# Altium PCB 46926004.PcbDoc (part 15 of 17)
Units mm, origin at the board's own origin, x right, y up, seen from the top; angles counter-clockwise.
Board outline 250 x 200 mm, 6 copper layers (Top Layer, INT1_GND, INT2_SIG, INT3_SIG, INT4_GND, Bottom Layer), stack 1.71 mm thick; 1450 components, 1293 nets, 5656 pads, 2307 vias.
Unrouted connection lines stored in the file: 2.
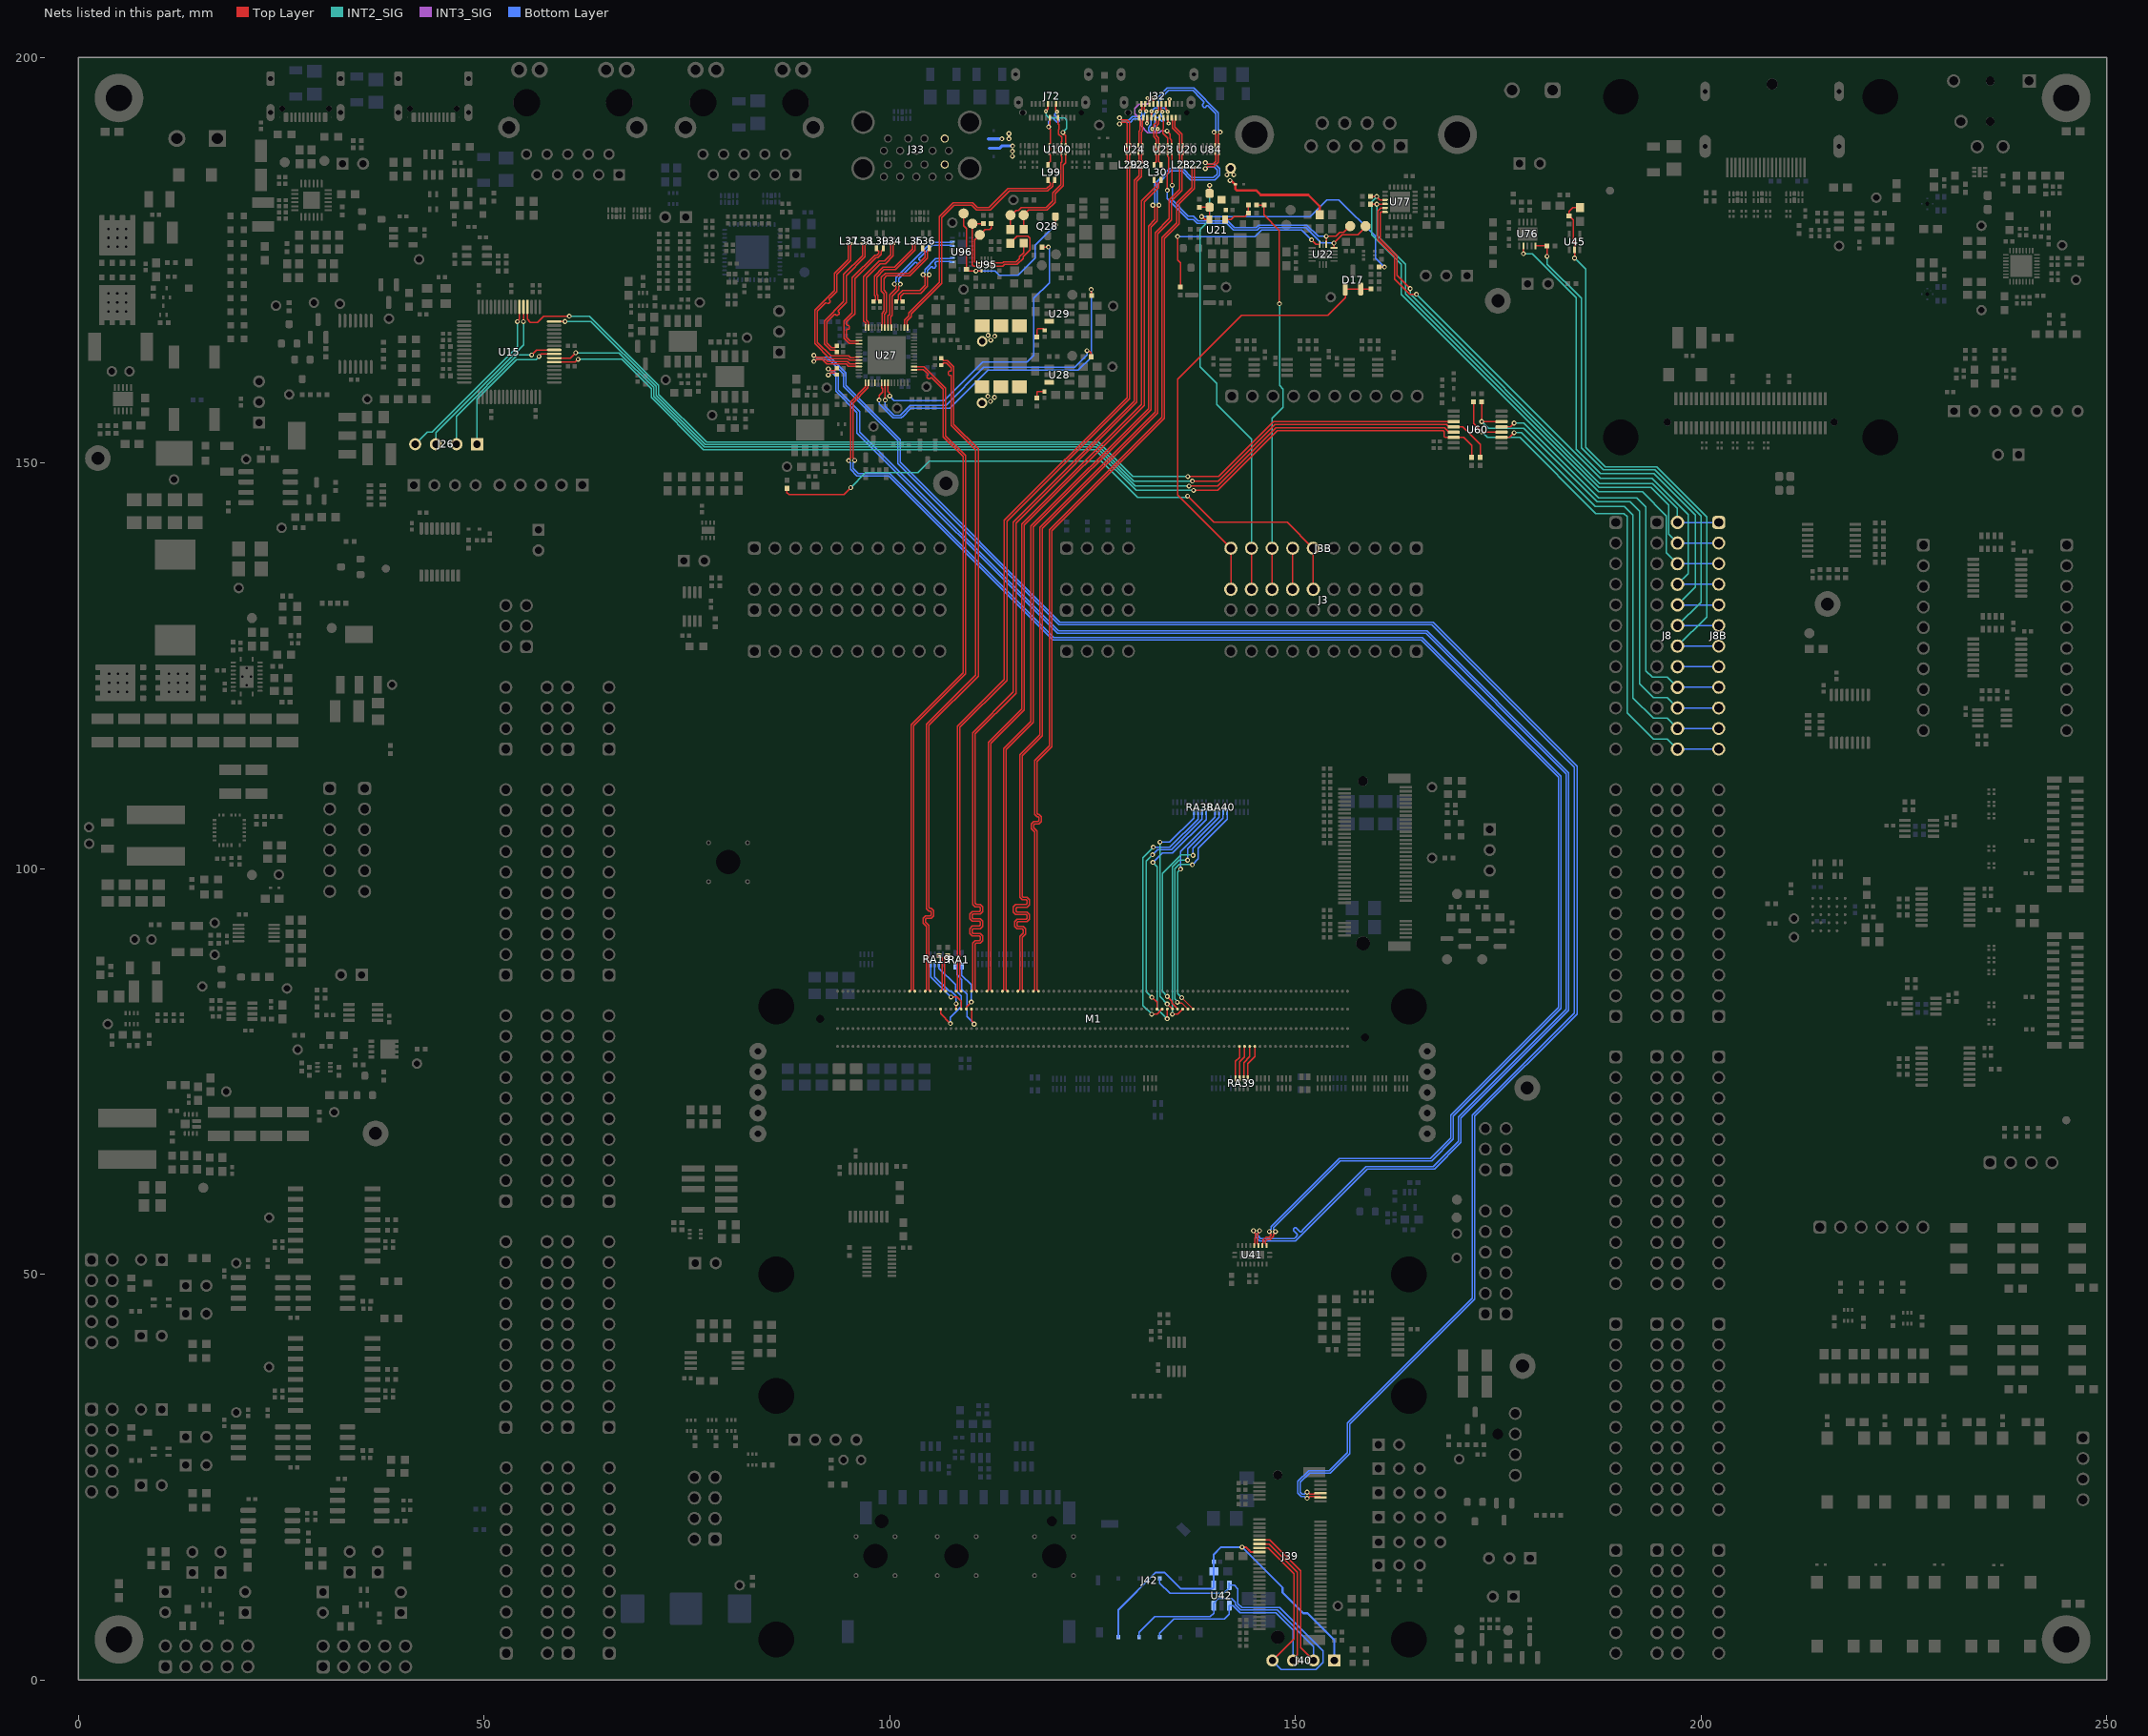
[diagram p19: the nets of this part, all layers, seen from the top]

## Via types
v1: diameter 0.6, hole 0.3, Top Layer to Bottom Layer, tented both sides, 2171 vias
v2: diameter 0.6, hole 0.3, Top Layer to Bottom Layer, 48 vias
v3: diameter 1, hole 0.5, Top Layer to Bottom Layer, tented both sides, 37 vias
v4: diameter 0.5, hole 0.2, Top Layer to Bottom Layer, tented both sides, 34 vias
v5: diameter 0.6, hole 0.3, Top Layer to Bottom Layer, tented bottom, 17 vias

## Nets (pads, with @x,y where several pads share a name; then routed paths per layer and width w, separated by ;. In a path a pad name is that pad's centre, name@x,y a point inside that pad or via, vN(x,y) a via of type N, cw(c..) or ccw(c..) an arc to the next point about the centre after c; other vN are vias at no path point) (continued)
SSRX2_N: J32.A10 L28.3 U24.1 U24.10 | length 5.7
  Top Layer w0.15: L28.3@131.15,187.125 131.075,187.2 131.075,187.288 131.05,187.313 131.05,187.996 131.15,188.096 U24.10@131.15,188.283 131.15,188.471 131.05,188.571 131.05,188.83 131.15,188.93 U24.1@131.15,189.117 131.15,189.305 131.05,189.405 131.05,190.809 131.15,190.909 131.15,192.187 131.175,192.212 131.175,192.475 J32.A10@131.25,192.55
SSRX2_P: J32.A11 L28.4 U24.2 U24.9 | length 5.7
  Top Layer w0.15: L28.4@130.65,187.125 130.725,187.2 130.725,187.288 130.75,187.313 130.75,187.996 130.65,188.096 U24.9@130.65,188.283 130.65,188.471 130.75,188.571 130.75,188.83 130.65,188.93 U24.2@130.65,189.117 130.65,189.305 130.75,189.405 130.75,190.933 130.85,191.034 130.85,192.187 130.825,192.212 130.825,192.475 J32.A11@130.75,192.55
SSTX1_N: J32.A3 L23.4 U20.5 U20.6 | length 6
  Top Layer w0.15: J32.A3@134.75,192.55 134.825,192.475 134.825,192.212 134.85,192.187 134.85,191.302 135.735,190.417 135.735,189.405 135.635,189.305 135.635,188.93 135.735,188.83 135.735,188.571 135.635,188.471 135.635,188.096 135.727,188.004 135.727,187.313 135.7,187.286 135.7,187.2 L23.4@135.625,187.125
SSTX1_P: J32.A2 L23.3 U20.4 U20.7 | length 6
  Top Layer w0.15: J32.A2@135.25,192.55 135.175,192.475 135.175,192.212 135.15,192.187 135.15,191.427 136.035,190.541 136.035,189.405 136.135,189.305 136.135,188.93 136.035,188.829 136.035,188.571 136.135,188.471 136.135,188.096 136.027,187.987 136.027,187.313 136.05,187.29 136.05,187.2 L23.3@136.125,187.125
SSTX2_N: J32.B3 L29.4 U24.5 U24.6 | length 11.6
  Top Layer w0.15: v1(128.32,191.805) 128.408,191.805 128.633,192.03 129.107,192.03 129.25,191.887 129.25,189.405 129.15,189.305 U24.5@129.15,189.117 129.15,188.93 129.25,188.83 129.25,188.571 129.15,188.471 U24.6@129.15,188.283 129.15,188.096 129.25,187.996 129.25,187.668 129.25,187.313 129.225,187.288 129.225,187.2 L29.4@129.15,187.125 ; J32.B3@131.5,194.25 131.425,194.175 131.425,193.916 131.396,193.887 131.396,193.613 131.6,193.409 v4(131.6,193.35)
  Bottom Layer w0.15: v1(128.32,191.805) 128.408,191.805 128.633,192.03 129.643,192.03 130.035,192.422 131.043,192.422 131.388,192.766 131.388,193.087 131.6,193.3 v4(131.6,193.35) 131.6,193.285 131.403,193.087
SSTX2_P: J32.B2 L29.3 U24.4 U24.7 | length 11.6
  Top Layer w0.15: v1(128.32,192.555) 128.408,192.555 128.633,192.33 129.231,192.33 129.55,192.011 129.55,189.405 129.65,189.305 U24.4@129.65,189.117 129.65,188.93 129.55,188.829 129.55,188.571 129.65,188.471 U24.7@129.65,188.283 129.65,188.096 129.55,187.995 129.55,187.792 129.55,187.313 129.575,187.288 129.575,187.2 L29.3@129.65,187.125 ; v4(130.875,193.35) 130.875,193.392 131.096,193.613 131.096,193.887 131.075,193.908 131.075,194.175 J32.B2@131,194.25
  Bottom Layer w0.15: v1(128.32,192.555) 128.408,192.555 128.633,192.33 129.519,192.33 129.911,192.722 130.919,192.722 131.088,192.891 131.088,193.087 130.875,193.3 v4(130.875,193.35) 130.875,193.285 131.073,193.087
UART3_CTS_3V: J26.4 U15.54 | length 22.6
  Top Layer w0.15: v1(54.09,167.435) 54.09,167.488 54.35,167.748 U15.54@54.35,169.25
  INT2_SIG w0.15: J26.4@41.515,152.325 43.015,153.825 43.594,153.825 54.09,164.321 v1(54.09,167.435)
UART3_RTS_3V: J26.3 U15.53 | length 21.4
  Top Layer w0.15: v1(54.85,167.435) U15.53@54.85,169.25
  INT2_SIG w0.15: J26.3@44.055,152.325 44.055,153.765 54.85,164.56 v1(54.85,167.435)
UART3_RXD_3V: R454.2 U15.48 U60.12 | length 128.4
  Top Layer w0.15: U15.48@58.65,167.45 v1(59.965,167.45) ; v1(137.3,147.775) 140.464,147.775 147.444,154.755 168.636,154.755 168.936,154.455 U60.12@169.5,154.455 170.629,154.455 172.782,152.303 R454.2@172.782,150.705
  INT2_SIG w0.15: v1(59.965,167.45) 63.19,167.45 71.2,159.44 71.2,158.349 77.277,152.272 125.577,152.272 130.074,147.775 v1(137.3,147.775)
UART3_TXD_3V: U15.52 U60.11 | length 127.8
  Top Layer w0.15: U15.52@55.35,169.25 55.35,168.177 55.325,168.152 55.325,167.718 55.699,167.344 56.574,167.344 57.335,168.105 v1(60.51,168.105) ; v1(136.735,148.328) 140.522,148.328 147.299,155.105 U60.11@169.5,155.105
  INT2_SIG w0.15: v1(60.51,168.105) 62.999,168.105 71.528,159.576 71.528,158.484 77.413,152.6 125.713,152.6 129.984,148.328 v1(136.735,148.328)
UART4_CTS_3V: J26.2 U15.41 | length 18.9
  Top Layer w0.15: v1(55.865,163.325) 56.49,163.95 U15.41@58.65,163.95
  INT2_SIG w0.15: J26.2@46.595,152.325 46.595,155.782 54.138,163.325 v1(55.865,163.325)
UART4_RTS_3V: J26.1 U15.40 | length 17.4
  Top Layer w0.15: v1(56.765,163.15) 56.778,163.15 57.078,163.45 U15.40@58.65,163.45
  INT2_SIG w0.15: J26.1@49.135,152.325 49.135,157.898 54.006,162.769 56.384,162.769 v1(56.765,163.15)
UART4_RXD_3V: R453.2 U15.38 U60.14 | length 126.2
  Top Layer w0.15: U15.38@58.65,162.45 61.235,162.45 v1(61.585,162.8) ; v1(137.436,146.634) 137.471,146.67 140.42,146.67 147.755,154.005 168.204,154.005 168.348,153.861 168.348,153.259 168.452,153.155 U60.14@169.5,153.155 170.75,153.155 171.726,152.179 R453.2@171.726,150.705
  INT2_SIG w0.15: v1(61.585,162.8) 66.992,162.8 70.6,159.192 70.6,158.1 77.028,151.672 125.328,151.672 130.366,146.634 v1(137.436,146.634)
UART4_TXD_3V: U15.39 U60.13 | length 121.8
  Top Layer w0.15: U15.39@58.65,162.95 60.65,162.95 v1(61.3,163.6) ; v1(136.872,147.159) 140.414,147.159 147.61,154.355 168.39,154.355 168.94,153.805 U60.13@169.5,153.805
  INT2_SIG w0.15: v1(61.3,163.6) 66.616,163.6 70.9,159.316 70.9,158.224 77.152,151.972 125.452,151.972 130.265,147.159 v1(136.872,147.159)
UART_1_CTS: M1.B36 RA38.1 | length 30.9
  Top Layer w0.15: v1(134.195,81.501) 134.201,81.507 134.201,82.694 M1.B36@134.207,82.7
  INT2_SIG w0.15: v1@132.4,100.8 132.95,100.25 132.95,82.747 v1(134.195,81.501)
  Bottom Layer w0.15: v1(132.428,100.772) 133.581,101.925 134.84,101.925 138.99,106.075 RA38.1@138.99,107
UART_1_CTS_JMP: J8.8 J8B.4 U77.11 | length 72.8
  Top Layer w0.15: U77.11@161.075,181.45 160.91,181.45 160.885,181.425 160.865,181.445 160.52,181.445 160.14,181.065 160.14,177.49 162.21,175.419 162.21,172.7 164.095,170.815 v1(164.915,170.815)
  INT2_SIG w0.15: v1(164.915,170.815) 187.63,148.1 193.951,148.1 198.4,143.651 198.4,136.37 J8.8@197.09,135.06
  Bottom Layer w0.15: J8.8@197.09,135.06 J8B.4@202.17,135.06
UART_1_RTS: M1.B38 RA38.2 | length 28.7
  Top Layer w0.15: v1(132.308,84.15) 132.937,83.521 M1.B38@132.937,82.7
  INT2_SIG w0.15: v1(132.308,84.15) 131.6,84.858 131.6,100.939 v1(132.383,101.722)
  Bottom Layer w0.15: v1(132.383,101.722) 133.011,102.35 134.74,102.35 138.49,106.1 RA38.2@138.49,107
UART_1_RTS_JMP: J8.6 J8B.3 R384.1 U77.9 | length 71.3
  Top Layer w0.15: R384.1@159.25,182.85 v1(160.018,182.85) 160.418,182.45 U77.9@160.885,182.45 U77.9@161.075,182.45
  INT2_SIG w0.15: v1(160.018,182.85) 159.39,182.222 159.39,178.13 163.036,174.484 163.036,170.792 187.376,146.451 192.746,146.451 195.707,143.49 195.707,138.982 J8.6@197.09,137.6
  Bottom Layer w0.15: J8.6@197.09,137.6 J8B.3@202.17,137.6
UART_1_RXD: M1.B35 RA38.4 | length 27.4
  Top Layer w0.15: v1(134.195,83.328) 134.214,83.328 M1.B35@134.842,82.7
  INT2_SIG w0.15: v1(133.293,103.275) 133.293,84.23 v1(134.195,83.328)
  Bottom Layer w0.15: v1(133.293,103.275) 134.512,103.275 137.49,106.253 RA38.4@137.49,107
UART_1_RXD_JMP: J8.2 J8B.1 U77.12 | length 62.9
  Top Layer w0.15: U77.12@161.075,180.95 U77.12@160.885,180.95 160.558,180.95 160.44,180.832 160.44,177.614 162.51,175.544 162.51,173.143 v1(164.15,171.503)
  INT2_SIG w0.15: v1(164.15,171.503) 164.15,170.838 187.488,147.5 194,147.5 197.09,144.41 J8.2@197.09,142.68
  Bottom Layer w0.15: J8.2@197.09,142.68 J8B.1@202.17,142.68
UART_1_TXD: M1.B37 RA38.3 | length 30.9
  Top Layer w0.15: v1(132.287,82.072) 132.944,82.072 M1.B37@133.572,82.7
  INT2_SIG w0.15: v1(132.287,82.072) 131.199,83.16 131.199,101.369 v1(132.481,102.65)
  Bottom Layer w0.15: v1(132.481,102.65) 134.512,102.65 137.99,106.128 RA38.3@137.99,107
UART_1_TXD_JMP: J8.4 J8B.2 R383.1 U77.10 | length 67.8
  Top Layer w0.15: R383.1@159.25,181.9 v1(160.025,181.9) 160.051,181.925 161.05,181.925 U77.10@161.075,181.95
  INT2_SIG w0.15: v1(160.025,181.9) 160.025,178.075 163.578,174.522 163.578,170.864 187.442,147 193.833,147 196.007,144.826 196.007,141.222 J8.4@197.09,140.14
  Bottom Layer w0.15: J8.4@197.09,140.14 J8B.2@202.17,140.14
UART_2_CTS: M1.B32 RA40.1 | length 28.9
  Top Layer w0.18: v1(135.448,83.53) 135.529,83.449 135.998,83.449 M1.B32@136.747,82.7
  INT2_SIG w0.15: v1(135.448,83.53) 135.448,83.643 135.148,83.944 135.148,99.991 135.687,100.53 137.238,100.53 v1(137.285,100.484)
  Bottom Layer w0.15: v1(137.285,100.484) 138.005,101.204 138.005,102.552 141.58,106.128 RA40.1@141.58,107
UART_2_CTS_JMP: J8.16 J8B.8 | length 5.1
  Bottom Layer w0.15: J8.16@197.09,124.9 J8B.8@202.17,124.9
UART_2_RTS: M1.B34 RA40.2 | length 29.1
  Top Layer w0.15: v1(134.214,84.255) 134.774,83.695 134.774,83.403 M1.B34@135.477,82.7
  INT2_SIG w0.15: v1(134.214,84.255) 133.593,84.876 133.593,99.389 135.926,101.722 137.31,101.722 v1(137.383,101.65)
  Bottom Layer w0.15: v1(137.383,101.65) 137.383,102.552 141.08,106.25 RA40.2@141.08,107
UART_2_RTS_JMP: J8.14 J8B.7 R343.1 R407.2 U45.2 | length 72.4
  Top Layer w0.15: v1(184.4,175.265) U45.2@184.4,176.3 184.4,177.25 184.25,177.4 184.25,179.95 R343.1@183.725,180.475 183.725,181.01 184.196,181.481 R407.2@185.05,181.481
  INT2_SIG w0.15: v1(184.4,175.265) 185.781,173.884 185.781,151.928 188.187,149.523 194.51,149.523 200.7,143.332 200.7,131.05 J8.14@197.09,127.44
  Bottom Layer w0.15: J8.14@197.09,127.44 J8B.7@202.17,127.44
UART_2_RXD: M1.B31 RA40.4 | length 27
  Top Layer w0.18: v1(135.986,84.109) 135.986,84.096 M1.B31@137.382,82.7
  INT2_SIG w0.15: v1(135.85,99.95) 135.478,99.578 135.478,84.618 v1(135.986,84.109)
  Bottom Layer w0.15: v1(135.85,99.95) 135.85,102.14 140.08,106.37 RA40.4@140.08,107
UART_2_RXD_JMP: J8.10 J8B.5 U76.2 | length 63.5
  Top Layer w0.15: v1(178.1,175.815) U76.2@178.1,176.783
  INT2_SIG w0.15: v1(178.1,175.815) 179.185,175.815 184.6,170.4 184.6,151.724 187.624,148.7 194.16,148.7 199.285,143.575 199.285,134.715 J8.10@197.09,132.52
  Bottom Layer w0.15: J8.10@197.09,132.52 J8B.5@202.17,132.52
UART_2_TXD: M1.B33 RA40.3 | length 29.4
  Top Layer w0.15: v1(134.833,82.072) 135.484,82.072 M1.B33@136.112,82.7
  INT2_SIG w0.15: v1(134.833,82.072) 134.848,82.087 134.848,100.22 135.683,101.055 v1(136.7,101.055)
  Bottom Layer w0.15: v1(136.7,101.055) 136.7,102.458 140.58,106.338 RA40.3@140.58,107
UART_2_TXD_JMP: J8.12 J8B.6 R432.1 U76.5 | length 66.1
  Top Layer w0.15: U76.5@179.6,176.783 180.998,176.783 R432.1@181,176.781 v1(181,175.475)
  INT2_SIG w0.15: v1(181,175.475) 181.038,175.438 181.038,174.512 185.245,170.305 185.245,151.869 187.952,149.162 194.288,149.162 199.977,143.473 199.977,132.867 J8.12@197.09,129.98
  Bottom Layer w0.15: J8.12@197.09,129.98 J8B.6@202.17,129.98
UART_3_RXD: M1.D19 RA39.1 | length 4.3
  Top Layer w0.15: RA39.1@144.125,74.15 144.125,75.96 145.002,76.837 M1.D19@145.002,78.1
UART_3_RXD_JMP: J8.18 J8B.9 U60.5 | length 52.3
  Top Layer w0.15: U60.5@175.4,154.455 176.479,154.455 v1(176.958,154.934)
  INT2_SIG w0.15: v1(176.958,154.934) 178.167,154.934 187.37,145.731 192.069,145.731 193.2,144.6 193.2,124.4 193.98,123.62 195.829,123.62 J8.18@197.09,122.36
  Bottom Layer w0.15: J8.18@197.09,122.36 J8B.9@202.17,122.36
UART_3_TXD: M1.D20 RA39.2 | length 4.3
  Top Layer w0.15: RA39.2@143.625,74.15 143.625,76.103 144.367,76.845 M1.D20@144.367,78.1
UART_3_TXD_JMP: J8.20 J8B.10 R455.2 U60.6 | length 61.2
  Top Layer w0.15: R455.2@172.95,157.55 172.958,157.542 v1(172.958,155.113) ; v1@172.954,155.109 175.396,155.109 U60.6@175.4,155.105
  INT2_SIG w0.15: v1(172.958,155.113) 172.985,155.113 173.816,154.281 178.12,154.281 187.165,145.237 191.251,145.237 192.408,144.08 192.408,122.772 194.1,121.08 195.829,121.08 J8.20@197.09,119.82
  Bottom Layer w0.15: J8.20@197.09,119.82 J8B.10@202.17,119.82
UART_4_RXD: M1.D21 RA39.3 | length 4.2
  Top Layer w0.15: RA39.3@143.125,74.15 143.125,76.196 143.732,76.803 M1.D21@143.732,78.1
UART_4_RXD_JMP: J8.22 J8B.11 U60.3 | length 55.3
  Top Layer w0.15: U60.3@175.4,153.155 176.363,153.155 v1(176.958,153.75)
  INT2_SIG w0.15: v1(176.958,153.75) 177.852,153.75 186.931,144.671 190.529,144.671 191.6,143.6 191.6,121.04 194.1,118.54 195.829,118.54 J8.22@197.09,117.28
  Bottom Layer w0.15: J8.22@197.09,117.28 J8B.11@202.17,117.28
UART_4_TXD: M1.D22 RA39.4 | length 4.1
  Top Layer w0.15: RA39.4@142.625,74.15 142.625,76.256 143.097,76.728 M1.D22@143.097,78.1
UART_4_TXD_JMP: J8.24 J8B.12 R456.2 U60.4 | length 66.1
  Top Layer w0.15: R456.2@171.95,157.55 171.95,154.869 v1(172.958,153.861) ; v1@172.986,153.833 175.372,153.833 U60.4@175.4,153.805
  INT2_SIG w0.15: v1(172.958,153.861) 173.669,153.15 177.652,153.15 187.002,143.8 190.498,143.8 190.9,143.398 190.9,119.2 194.1,116 195.829,116 J8.24@197.09,114.74
  Bottom Layer w0.15: J8.24@197.09,114.74 J8B.12@202.17,114.74
UIM_CLK: J39.32 J40.3 J42.C3 U42.1 | length 41.2
  Top Layer w0.15: J39.32@145.55,16.775 146.757,16.775 150.23,13.302 150.23,3.124 149.7,2.594 J40.3@149.7,2.4
  Bottom Layer w0.15: J42.C3@133.27,5.275 133.27,5.77 135,7.5 141.241,7.5 141.841,8.1 U42.1@141.841,9.163 142.306,9.163 143.161,8.308 147.562,8.308 149.7,6.17 J40.3@149.7,2.4
UIM_DATA: J39.34 J40.4 J42.C7 U42.6 | length 52.4
  Top Layer w0.15: J39.34@145.55,16.275 146.65,16.275 149.8,13.125 149.8,5.04 J40.4@147.16,2.4
  Bottom Layer w0.15: J42.C7@133.27,12.535 133.27,11.93 134.532,10.668 141.151,10.668 141.841,11.358 U42.6@141.841,11.673 ; U42.6@141.841,11.988 U42.6@141.841,11.673 ; J40.4@147.16,2.4 148.26,1.3 152.519,1.3 153.4,2.181 153.4,3.57 148.048,8.922 143.396,8.922 142.889,9.428 142.889,11.246 142.462,11.673 U42.6@141.841,11.673
UIM_PWR: C197.1 J39.36 J40.1 J42.C1 R191.1 U42.4 | length 47.3
  Top Layer w0.25: v1(143.418,16.375) 143.897,16.375 144.295,15.977 144.497,15.775 J39.36@145.55,15.775
  Bottom Layer w0.25: J42.C1@128.19,5.275 128.19,8.665 132.796,13.271 133.854,13.271 135.893,11.232 139.776,11.232 139.941,11.397 R191.1@139.941,13.375 C197.1@139.941,14.592 139.941,15.485 140.831,16.375 v1(143.418,16.375) 148.41,11.382 148.41,10.775 150.96,8.225 151.496,8.225 154.78,4.941 J40.1@154.78,2.4
UIM_RST: J39.30 J40.2 J42.C2 U42.3 | length 47.3
  Top Layer w0.15: J39.30@145.55,17.275 146.825,17.275 150.65,13.45 150.65,3.99 J40.2@152.24,2.4
  Bottom Layer w0.15: J42.C2@130.73,5.275 130.73,5.852 132.678,7.8 139.5,7.8 139.941,8.241 U42.3@139.941,9.163 139.941,9.478 140.482,10.019 142.155,10.019 142.589,9.586 142.589,9.304 143.271,8.622 147.753,8.622 152.24,4.135 J40.2@152.24,2.4
USB1_CC1: J32.A5 U22.13 U23.2 U23.9 X39.1 | length 38.8
  Top Layer w0.15: J32.A5@133.75,192.55 133.75,191.238 133.662,191.151 133.662,190.677 134.25,190.09 U23.2@134.25,189.117 U23.9@134.25,188.283 134.25,187.8 134.35,187.7 134.35,185.794 134.213,185.657 v1(134.213,183.63) ; U22.13@154.746,176.515 v1(154.746,177.115) 155.754,178.123 157.669,178.123 158.646,179.1 X39.1@158.646,179.215
  Bottom Layer w0.15: v1(134.213,183.63) 134.213,182.578 136.759,180.033 137.433,180.033 137.916,179.55 141.512,179.55 142.359,178.703 145.289,178.703 145.612,179.025 151.283,179.025 153.193,177.115 v1(154.746,177.115)
USB1_CC2: J32.B5 U22.14 U23.1 U23.10 X38.1 | length 44.1
  Top Layer w0.15: J32.B5@132.5,194.25 v4(132.5,195.005) ; v1(134.187,190.933) 134.187,190.916 134.55,190.554 134.55,189.988 134.75,189.788 U23.1@134.75,189.117 U23.10@134.75,188.283 134.781,188.252 134.781,184.277 v1(134.813,184.246) ; U22.14@153.796,176.965 153.804,176.973 153.804,177.933 v1(153.812,177.941) 154.966,177.941 155.448,178.423 155.954,178.423 X38.1@156.746,179.215
  INT3_SIG w0.15: v4(132.5,195.005) 131.73,194.235 130.699,194.235 130.183,193.718 130.183,193.049 130.943,192.289 130.943,191.586 131.814,190.714 133.204,190.714 133.424,190.933 v1(134.187,190.933)
  Bottom Layer w0.15: v1(134.813,184.246) 134.813,182.443 136.804,180.451 137.439,180.451 138.04,179.85 141.636,179.85 142.483,179.003 145.165,179.003 145.487,179.325 151.407,179.325 152.791,177.941 v1(153.812,177.941)
USB1_OC#: JP1.2 R108.2 R111.2 U21.3 | length 32.9
  Top Layer w0.15: R108.2@138.145,181.536 JP1.2@139.42,181.536 U21.3@139.42,180.036 138.845,180.036 138.506,180.375 v1(138.443,180.375) ; R111.2@160.299,174.163 v1@160.964,174.163
  Bottom Layer w0.15: v1(138.443,180.375) 151.817,180.375 153.885,182.443 155.363,182.443 159.866,177.94 159.866,175.261 v1(160.966,174.16)
USB1_VBUS: C31.2 C100.2 D50.2 J32.A4 J32.A9 J32.B4 J32.B9 R110.2 R119.2 R452.1 U21.1 X41.1 | length 20.9
  Top Layer w0.15: U21.1@141.32,180.036 142.068,180.036 142.406,180.373 143.768,180.373 R119.2@144.195,180.8 144.192,180.803 144.192,181.807 R452.1@144.19,181.81
  Top Layer w0.25: J32.A4@134.25,192.55 134.275,192.525 134.275,192.018 134.375,191.918 v4(134.375,191.85)
  Top Layer w0.3: v4(131.7,191.9) 131.7,191.954 131.75,192.004 J32.A9@131.75,192.55 ; v4(131.77,194.982) 131.77,194.928 132,194.697 J32.B4@132,194.25 ; J32.B9@134.5,194.25 v4(134.5,194.85) ; v1(141.935,184.828) 141.992,184.77 142.152,184.77 142.567,184.355 D50.2@142.66,184.355 ; D50.2@142.614,184.355 142.614,183.766 142.789,183.59 145.195,183.59 145.736,183.049 151.587,183.049 152.996,181.64 R110.2@152.996,180.59
  other v1: 141.561,185.525 142.409,185.525
USB3_CC1: J72.A5 R436.1 U100.2 U100.9 X106.1 | length 18.6
  Top Layer w0.15: R436.1@114.889,178.794 X106.1@114.889,180.566 114.991,180.566 115.541,181.116 115.843,181.116 116.21,181.482 119.267,181.482 120.075,182.29 120.075,183.312 121.076,184.312 121.076,187.001 121.2,187.125 121.2,187.775 121.175,187.8 U100.9@121.175,188.283 U100.2@121.175,189.117 121.175,189.608 121.2,189.633 121.2,190.17 120.825,190.545 120.825,191.105 120.857,191.138 120.857,191.698 120.75,191.805 J72.A5@120.75,192.55
USB3_CC2: J72.B5 R437.1 U100.1 U100.10 X105.1 | length 21.6
  Top Layer w0.15: R437.1@116.495,178.812 X105.1@116.495,180.566 117.112,181.182 119.391,181.182 120.375,182.166 120.375,183.187 121.376,184.188 121.376,186.736 121.675,187.035 U100.10@121.675,188.283 U100.1@121.675,189.117 121.675,190.345 121.35,190.67 v1(121.35,190.763) ; v4(119.25,193.35) 119.25,193.425 119.5,193.675 J72.B5@119.5,194.25
  INT2_SIG w0.15: v4(119.25,193.35) 119.281,193.319 119.281,192.875 119.606,192.55 121.562,192.55 121.825,192.287 121.825,191.238 v1(121.35,190.763)
USB3_ID: Q28.1 R377.1 U95.9 X98.1 | length 23.5
  Top Layer w0.15: X98.1@109.099,180.765 109.099,179.271 109.456,178.914 R377.1@109.456,173.897 109.681,173.672 110.619,173.672 v1(110.626,173.665) 110.649,173.688 111.293,173.688 U95.9@111.316,173.711 ; Q28.1@120.417,180.392 120.421,180.388 120.421,179.375 v1(120.425,179.371)
  Bottom Layer w0.15: v1(110.626,173.665) 113,173.665 113.495,173.171 115.805,173.171 117.907,175.273 117.907,176.854 v1(120.425,179.371)
USB3_N: L99.3 U27.2 | length 32
  Top Layer w0.15: U27.2@101.794,166.694 101.821,166.721 101.821,167.077 101.844,167.1 101.844,167.644 102.37,168.17 102.37,168.534 106.126,172.29 106.126,180.403 107.824,182.1 110.213,182.1 110.813,181.5 112.248,181.5 114.597,183.849 119.344,183.849 119.775,184.28 119.775,184.512 119.687,184.6 119.625,184.6 119.5,184.725 L99.3@119.5,184.9
USB3_OUT1: R375.1 U95.7 X100.1 | length 6.7
  Top Layer w0.15: U95.7@111.266,174.661 110.692,174.661 110.487,174.865 110.487,177.505 111.777,178.794 112.316,178.794 112.495,178.972 R375.1@112.495,179.512
USB3_OUT2: R376.1 U95.8 X99.1 | length 7.6
  Top Layer w0.15: U95.8@111.266,174.261 110.352,174.261 110.187,174.425 110.187,179.51 X99.1@110.19,179.512 111.551,179.512 R376.1@111.554,179.51
USB3_P: L99.2 U27.1 | length 32
  Top Layer w0.15: U27.1@102.194,166.694 102.167,166.721 102.167,167.077 102.144,167.1 102.144,167.519 102.67,168.045 102.67,168.41 106.426,172.166 106.426,180.279 107.948,181.8 110.088,181.8 110.688,181.2 112.372,181.2 114.721,183.549 119.469,183.549 120.075,184.156 120.075,184.512 120.163,184.6 120.225,184.6 120.35,184.725 L99.2@120.35,184.9
USB3_PRTPWR: R433.2 U27.36 | length 37
  Top Layer w0.15: U27.36@99.794,159.891 99.794,158.795 99.92,158.669 99.92,158.351 v1(100.006,158.265) ; R433.2@118.764,176.626 v1(119.547,176.626) ; R433.2@118.866,176.679 R433.2@118.877,176.69
  Bottom Layer w0.15: v1(100.006,158.265) 100.547,157.724 106.684,157.724 111.435,162.475 116.945,162.475 117.771,163.3 117.771,170.34 119.66,172.229 v1@119.66,176.69
USB3_SSRX_N: U27.7 U96.8 | length 15.5
  Top Layer w0.15: U27.7@99.794,166.694 99.794,168.172 99.98,168.358 99.98,170.712 100.792,171.524 100.792,171.746 100.567,171.971 v1(100.567,172.059)
  Bottom Layer w0.15: v1(100.567,172.059) 100.567,172.162 100.777,172.372 100.777,172.855 105.112,177.19 107.445,177.19 107.53,177.275 U96.8@107.71,177.275
USB3_SSRX_P: U27.6 U96.7 | length 15.5
  Top Layer w0.15: U27.6@100.194,166.694 100.194,166.996 100.121,167.069 100.121,167.161 100.094,167.188 100.094,168.048 100.28,168.234 100.28,170.588 101.092,171.4 101.092,171.734 101.317,171.959 v1(101.317,172.047)
  Bottom Layer w0.15: v1(101.317,172.047) 101.317,172.15 101.107,172.36 101.107,172.719 102.707,174.318 103.113,174.725 103.255,174.725 103.383,174.596 103.525,174.596 103.737,174.808 103.737,174.95 103.608,175.078 103.608,175.22 104.011,175.623 105.249,176.86 107.445,176.86 107.53,176.775 U96.7@107.71,176.775
USB3_SSTX_N: C131.1 U96.4 | length 10.8
  Top Layer w0.15: C131.1@100.792,169.925 101.03,170.162 101.03,170.711 101.559,171.24 103.682,171.24 104.335,171.892 104.335,172.909 104.112,173.132 v1(104.112,173.222)
  Bottom Layer w0.15: v1(104.112,173.222) 104.112,173.325 104.322,173.535 104.322,173.872 105.64,175.19 107.445,175.19 107.53,175.275 U96.4@107.71,175.275
USB3_SSTX_P: C135.1 U96.3 | length 10.8
  Top Layer w0.15: C135.1@101.567,169.925 101.33,170.162 101.33,170.587 101.684,170.94 103.807,170.94 104.635,171.768 104.635,172.897 104.862,173.124 v1(104.862,173.21)
  Bottom Layer w0.15: v1(104.862,173.21) 104.862,173.313 104.652,173.523 104.652,173.735 104.689,173.773 105.096,174.179 105.237,174.179 105.372,174.045 105.513,174.045 105.725,174.257 105.725,174.399 105.591,174.533 105.591,174.674 105.691,174.774 105.777,174.86 106.217,174.86 107.445,174.86 107.53,174.775 U96.3@107.71,174.775
USB4_5V: C32.2 C145.2 C190.2 C198.2 D38.2 J33.U1 R144.2 U28.6 X52.1 | length 4.7
  Top Layer w0.15: R144.2@118.129,158.03 118.129,158.743 118.217,158.83 C145.2@119.069,158.83
  Bottom Layer w0.4: 112.267,188.8 D38.2@112.834,188.8 113.495,188.8 113.789,189.095 v1(115.136,189.095)
  other v1: 112.404,157.605 112.9,158.104 112.096,158.238 115.125,187.818 115.125,188.444
USB4_N: L36.3 U27.9 | length 14.1
  Top Layer w0.15: U27.9@98.994,166.694 99.021,166.721 99.021,167.077 99.041,167.097 99.041,168.448 99.317,168.725 99.317,170.832 98.967,171.182 98.967,172.887 99.478,173.397 102.362,173.397 104.325,175.36 104.325,176.087 104.237,176.175 104.175,176.175 104.05,176.3 L36.3@104.05,176.475
USB4_P: L36.2 U27.8 | length 14.1
  Top Layer w0.15: U27.8@99.394,166.694 99.367,166.721 99.367,167.077 99.341,167.103 99.341,168.324 99.617,168.6 99.617,170.956 99.267,171.306 99.267,172.762 99.602,173.097 102.486,173.097 104.625,175.236 104.625,176.087 104.713,176.175 104.775,176.175 104.9,176.3 L36.2@104.9,176.475
USB4_PRTPWR: R220.2 U27.35 | length 33
  Top Layer w0.15: U27.35@99.394,159.891 99.394,159.332 99.442,159.284 v1(99.442,157.77) ; v1(124.301,163.841) 124.387,163.755 124.677,163.755 124.803,163.629 124.803,163.123 R220.2@124.822,163.104
  Bottom Layer w0.15: v1(99.442,157.77) 99.442,156.989 100.545,155.887 101.269,155.887 102.509,157.127 106.924,157.127 111.598,161.8 122.779,161.8 124.295,163.316 124.295,163.835 v1(124.301,163.841)
USB4_SSRX_N: L34.3 U27.14 | length 12.3
  Top Layer w0.15: U27.14@96.994,166.694 97.021,166.721 97.021,167.077 97.044,167.1 97.044,167.261 96.794,167.511 96.794,172.974 98.705,174.885 99.358,174.885 100.13,175.657 100.13,176.887 100.105,176.912 100.105,177 L34.3@100.03,177.075
USB4_SSRX_P: L34.4 U27.13 | length 12.3
  Top Layer w0.15: U27.13@97.394,166.694 97.367,166.721 97.367,167.077 97.344,167.1 97.344,167.385 97.094,167.635 97.094,172.85 98.829,174.585 99.482,174.585 100.43,175.533 100.43,176.887 100.455,176.912 100.455,177 L34.4@100.53,177.075
USB4_SSTX_N: C132.1 L35.3 | length 10.1
  Top Layer w0.15: C132.1@97.992,169.925 98.242,170.175 98.242,170.534 98.092,170.684 98.092,173.037 99.185,174.13 100.582,174.13 102.825,176.373 102.825,176.887 102.8,176.912 102.8,177 L35.3@102.725,177.075
USB4_SSTX_P: C136.1 L35.4 | length 10.1
  Top Layer w0.15: C136.1@98.792,169.925 98.542,170.175 98.542,170.658 98.392,170.809 98.392,172.912 99.31,173.83 100.706,173.83 103.125,176.249 103.125,176.887 103.15,176.912 103.15,177 L35.4@103.225,177.075
USB5_5V: C33.2 C146.2 C191.2 C199.2 D37.2 J33.L1 R145.2 U29.6 X53.1 | length 3.3
  Top Layer w0.15: R145.2@118.129,165.559 118.129,166.458 118.217,166.546 118.571,166.546 118.573,166.544 118.927,166.544 C146.2@119.112,166.359
  Bottom Layer w0.4: 112.172,189.974 D37.2@112.834,189.974 113.495,189.974
  other v1: 112.45,165.144 112.946,165.642 112.123,165.747 113.827,189.974 114.69,189.974 114.69,190.6
USB5_N: L39.3 U27.18 | length 15.3
  Top Layer w0.15: U27.18@96.193,164.693 96.166,164.72 95.81,164.72 95.787,164.743 95.01,164.743 94.361,165.392 94.361,167.506 95.383,168.528 95.383,172.833 98.175,175.625 98.413,175.625 98.63,175.842 98.63,176.087 98.542,176.175 98.48,176.175 98.355,176.3 L39.3@98.355,176.475
USB5_P: L39.2 U27.17 | length 15.3
  Top Layer w0.15: U27.17@96.193,165.093 96.166,165.066 95.81,165.066 95.787,165.043 95.134,165.043 94.661,165.516 94.661,165.807 94.661,166.382 94.761,166.482 94.927,166.482 95.027,166.582 95.027,166.882 94.927,166.982 94.761,166.982 94.661,167.082 94.661,167.382 95.194,167.914 95.683,168.404 95.683,172.709 98.299,175.325 98.537,175.325 98.93,175.718 98.93,176.087 99.018,176.175 99.08,176.175 99.205,176.3 L39.2@99.205,176.475
USB5_PRTPWR: R298.2 U27.34 | length 41.9
  Top Layer w0.15: v1(98.69,157.761) 98.701,157.772 98.701,158.33 99.119,158.748 99.119,159.182 98.994,159.307 U27.34@98.994,159.891 ; v1(124.826,171.403) 124.826,170.681 R298.2@124.861,170.646
  Bottom Layer w0.15: v1(98.69,157.761) 98.698,157.753 98.698,157.31 100.42,155.587 101.394,155.587 101.527,155.72 101.558,155.72 102.599,156.762 107.425,156.762 112.11,161.446 123.219,161.446 124.826,163.053 v1(124.826,171.403)
USB5_SSRX_N: L37.3 U27.23 | length 20.4
  Top Layer w0.15: L37.3@94.775,177.075 94.85,177 94.85,176.912 94.875,176.887 94.875,175.083 93.172,173.38 93.172,171.285 90.775,168.888 90.775,164.742 92.625,162.893 94.815,162.893 95.04,162.668 96.168,162.668 U27.23@96.193,162.693
USB5_SSRX_P: L37.4 U27.22 | length 20.4
  Top Layer w0.15: L37.4@95.275,177.075 95.2,177 95.2,176.912 95.175,176.887 95.175,174.958 93.472,173.256 93.472,171.161 92.785,170.474 92.563,170.252 92.563,170.11 92.665,170.008 92.665,169.866 92.453,169.654 92.312,169.654 92.209,169.757 92.068,169.757 91.661,169.35 91.075,168.764 91.075,164.866 92.749,163.193 94.939,163.193 95.164,162.968 95.619,162.968 95.721,163.07 96.17,163.07 U27.22@96.193,163.093
USB5_SSTX_N: C133.1 L38.3 | length 16.3
  Top Layer w0.15: C133.1@93.467,163.7 93.242,163.925 92.718,163.925 91.936,164.707 91.936,167.52 94.33,169.914 94.33,173.24 96.65,175.56 96.65,176.887 96.625,176.912 96.625,177 L38.3@96.55,177.075
USB5_SSTX_P: C137.1 L38.4 | length 16.3
  Top Layer w0.15: C137.1@93.467,164.45 93.242,164.225 92.842,164.225 92.236,164.831 92.236,167.396 92.757,167.917 93.163,168.323 93.305,168.323 93.422,168.206 93.563,168.206 93.775,168.418 93.775,168.56 93.658,168.677 93.658,168.818 94.007,169.167 94.63,169.79 94.63,173.116 96.95,175.436 96.95,176.887 96.975,176.912 96.975,177 L38.4@97.05,177.075
USB6_N: J39.9 U27.25 | length 231.5
  Top Layer w0.15: v1(90.641,162.522) 90.729,162.522 90.954,162.747 91.311,162.747 91.314,162.75 91.695,162.75 92.223,162.222 94.637,162.222 94.917,161.943 95.787,161.943 95.81,161.92 96.166,161.92 U27.25@96.193,161.893 ; v1(151.44,22.4) 151.562,22.4 151.787,22.625 152.312,22.625 152.337,22.6 153.025,22.6 J39.9@153.1,22.525
  Bottom Layer w0.15: v1(90.641,162.522) 90.729,162.522 90.954,162.747 91.744,162.747 91.747,162.75 92.56,162.75 94.307,161.002 94.307,159.456 101.009,152.754 101.009,149.966 120.876,130.1 166.83,130.1 184.394,112.536 184.394,82.212 171.81,69.627 171.81,47.058 156.4,31.649 156.4,28.031 154.188,25.82 151.645,25.82 150.311,24.486 150.311,23.023 150.709,22.625 151.128,22.625 151.353,22.4 v1(151.44,22.4)
USB6_P: J39.7 U27.24 | length 231.5
  Top Layer w0.15: v1(90.641,163.272) 90.729,163.272 90.954,163.047 91.187,163.047 91.19,163.05 91.819,163.05 92.347,162.522 94.762,162.522 95.041,162.243 95.787,162.243 95.81,162.266 96.166,162.266 U27.24@96.193,162.293 ; v1(151.44,23.15) 151.562,23.15 151.787,22.925 152.312,22.925 152.337,22.95 153.025,22.95 J39.7@153.1,23.025
  Bottom Layer w0.15: v1(90.641,163.272) 90.729,163.272 90.954,163.047 91.62,163.047 91.623,163.05 92.684,163.05 94.607,161.126 94.607,159.58 101.309,152.878 101.309,150.091 121,130.4 166.954,130.4 184.694,112.66 184.694,82.087 172.11,69.503 172.11,46.934 156.7,31.524 156.7,27.907 154.313,25.52 151.769,25.52 150.611,24.362 150.611,23.147 150.833,22.925 151.128,22.925 151.353,23.15 v1(151.44,23.15)
USB6_PRTPWR: U27.32
USB6_SSRX_N: U27.30 U41.12 | length 194.5
  Top Layer w0.15: v1(95.683,150.335) 95.683,150.423 95.458,150.648 95.458,157.404 97.321,159.267 97.321,159.516 97.394,159.589 U27.30@97.394,159.891 ; U41.12@146.423,53.55 146.423,53.73 146.323,53.83 146.323,54.099 146.533,54.309 146.905,54.309 147.313,54.717 147.313,54.959 147.538,55.184 v1(147.538,55.272)
  Bottom Layer w0.15: v1(95.683,150.335) 95.683,150.243 95.463,150.022 95.463,149.336 96.098,148.7 100,148.7 120.2,128.5 165.634,128.5 182.715,111.419 182.715,82.77 169.471,69.526 169.471,66.681 166.775,63.985 155.538,63.985 151.101,59.548 147.313,55.76 147.313,55.585 147.538,55.36 v1(147.538,55.272)
USB6_SSRX_P: U27.29 U41.13 | length 194.5
  Top Layer w0.15: v1(94.933,150.31) 94.933,150.399 95.158,150.623 95.158,157.528 97.017,159.388 97.017,159.868 U27.29@96.994,159.891 ; U41.13@145.923,53.55 145.923,53.73 146.023,53.83 146.023,54.224 146.409,54.609 146.781,54.609 147.013,54.841 147.013,54.959 146.788,55.184 v1(146.788,55.272)
  Bottom Layer w0.15: v1(94.933,150.31) 94.933,150.227 95.163,149.998 95.163,149.212 95.974,148.4 99.876,148.4 120.076,128.2 165.51,128.2 182.415,111.295 182.415,82.894 169.171,69.65 169.171,66.805 166.651,64.285 155.414,64.285 150.977,59.848 147.013,55.884 147.013,55.585 146.788,55.36 v1(146.788,55.272)
USB6_SSTX_N: C134.1 U41.14 | length 200.2
  Top Layer w0.15: v1(92.426,160.85) 92.514,160.85 92.739,161.075 93.068,161.075 93.095,161.103 93.219,161.103 93.24,161.082 93.307,161.082 C134.1@93.492,160.897 ; U41.14@145.423,53.55 145.423,53.73 145.323,53.83 145.323,54.367 145.348,54.392 145.348,55.062 145.573,55.287 v1(145.573,55.375)
  Bottom Layer w0.15: v1(92.426,160.85) 92.514,160.85 92.739,161.075 92.944,161.075 93.355,160.664 93.355,158.851 95.974,156.232 95.974,153.679 120.653,129 166.082,129 183.375,111.707 183.375,82.654 170.111,69.39 170.111,66.379 167.002,63.27 158.719,63.27 151.075,55.626 150.704,55.255 150.576,55.255 150.083,55.748 149.956,55.748 149.765,55.558 149.765,55.43 150.258,54.937 150.258,54.81 149.973,54.524 149.849,54.4 145.74,54.4 145.348,54.791 145.348,55.062 145.573,55.287 v1(145.573,55.375)
USB6_SSTX_P: C138.1 U41.15 | length 200.2
  Top Layer w0.15: v1(92.426,161.6) 92.514,161.6 92.739,161.375 92.944,161.375 92.971,161.403 93.198,161.403 C138.1@93.492,161.697 ; v1(144.823,55.375) 144.823,55.287 145.048,55.062 145.048,54.516 145.023,54.491 145.023,53.83 144.923,53.73 U41.15@144.923,53.55
  Bottom Layer w0.15: v1(92.426,161.6) 92.514,161.6 92.739,161.375 93.068,161.375 93.655,160.788 93.655,158.975 96.274,156.356 96.274,153.803 120.778,129.3 166.206,129.3 183.675,111.831 183.675,82.53 170.411,69.266 170.411,66.255 167.127,62.97 158.843,62.97 149.973,54.1 145.615,54.1 145.048,54.667 145.048,55.062 144.823,55.287 v1(144.823,55.375)
USB_1_CON_N: J32.A7 J32.B7 L30.4 U23.5 U23.6 | length 11.8
  Top Layer w0.15: L30.4@132.575,186.75 132.575,186.925 132.7,187.05 132.762,187.05 132.85,187.138 132.85,187.996 132.75,188.096 U23.6@132.75,188.283 132.75,188.471 132.85,188.571 132.85,188.83 132.75,188.93 U23.5@132.75,189.117 132.75,189.305 132.85,189.405 132.85,189.922 132.533,190.239 132.533,190.926 132.358,191.101 132.358,191.277 132.575,191.495 132.575,191.7 132.85,191.975 132.85,192.187 132.825,192.212 132.825,192.275 132.75,192.35 J32.A7@132.75,192.55 ; J32.B7@133.5,194.25 133.425,194.175 133.425,193.895 133.417,193.887 133.417,193.563 133.618,193.363 v4(133.618,193.3)
  Bottom Layer w0.15: v4(132.358,191.189) 132.533,191.364 132.533,191.386 132.675,191.528 132.675,192.187 132.675,192.357 132.926,192.608 133.067,192.608 133.565,192.11 133.707,192.11 133.848,192.251 133.848,192.392 133.35,192.891 133.35,193.032 v4(133.618,193.3)
USB_1_CON_P: J32.A6 J32.B6 L30.1 U23.4 U23.7 | length 12
  Top Layer w0.15: v4(132.917,193.3) 132.917,193.362 133.117,193.563 133.117,193.87 133.075,193.912 133.075,194.175 J32.B6@133,194.25 ; J32.A6@133.25,192.55 133.175,192.475 133.175,192.212 133.15,192.187 133.15,191.851 132.875,191.576 132.875,191.416 133.008,191.284 133.008,191.101 132.833,190.926 132.833,190.363 133.15,190.046 133.15,189.405 133.25,189.305 133.25,188.93 133.15,188.829 133.15,188.571 133.25,188.471 U23.7@133.25,188.283 133.25,188.096 133.15,187.995 133.15,187.262 133.15,187.138 133.238,187.05 133.3,187.05 133.425,186.925 L30.1@133.425,186.75
  Bottom Layer w0.15: v4(132.917,193.3) 132.917,193.296 132.183,192.561 132.183,191.664 132.161,191.664 131.883,191.386 131.883,190.992 132.161,190.714 132.554,190.714 132.833,190.992 132.833,191.24 132.841,191.249 132.85,191.257 132.939,191.257 v4(133.008,191.189)
USB_1_D_N: L30.3 M1.A71 | length 108.8
  Top Layer w0.15: M1.A71@111.983,84.9 111.983,84.923 112.15,85.091 112.15,96.392 112.15,101.618 112.15,115.574 116.286,119.71 116.286,142.457 131.05,157.222 131.05,182.307 132.85,184.107 132.85,184.512 132.762,184.6 132.7,184.6 132.575,184.725 L30.3@132.575,184.9
USB_1_D_P: L30.2 M1.A70 | length 108.8
  Top Layer w0.15: M1.A70@112.618,84.9 112.618,84.923 112.45,85.091 112.45,96.392 112.45,101.618 112.45,115.45 116.586,119.586 116.586,142.333 131.35,157.097 131.35,182.183 133.15,183.983 133.15,184.512 133.238,184.6 133.3,184.6 133.425,184.725 L30.2@133.425,184.9
USB_1_EN: M1.B77 RA19.3 | length 6.8
  Top Layer w0.15: M1.B77@108.172,82.7 108.178,82.706 108.178,83.349 v1(108.185,83.355)
  Bottom Layer w0.15: RA19.3@105.55,88.25 105.55,86.688 107.32,84.919 107.559,84.919 108.185,84.293 v1(108.185,83.355)
USB_1_EN_JMP: J3.13 J3B.7 | length 5.1
  Top Layer w0.15: J3.13@149.66,134.43 J3B.7@149.66,139.51
USB_1_EN_SRC: R105.2 U22.16 | length 24.9
  Top Layer w0.15: v1(135.475,177.933) 135.475,175.025 135.817,174.683 R105.2@135.815,171.703 R105.2@135.815,171.703 ; v1(151.971,177.515) 152.521,176.965 U22.16@152.896,176.965
  Bottom Layer w0.15: v1(135.475,177.933) 145.032,177.933 145.824,178.725 150.761,178.725 v1(151.971,177.515)
USB_1_INT#: M1.B74 RA1.2 | length 10.1
  Top Layer w0.15: M1.B74@110.077,82.7 110.077,81.267 110.395,80.949 v1(110.395,80.848)
  Bottom Layer w0.15: RA1.2@108.1,88 108.275,87.825 108.275,86.947 108.9,86.322 108.9,85.133 109.5,84.533 109.5,81.796 110.395,80.901 v1(110.395,80.848)
USB_1_INT#_JMP: D17.1 D17.2 J3.19 J3B.10 R118.2 | length 57.7
  Top Layer w0.15: J3.19@142.04,134.43 142.04,138.18 J3B.10@142.04,139.51 135.515,146.035 135.515,160.346 143.364,168.195 153.984,168.195 156.146,170.358 D17.1@156.146,171.465 D17.2@158.046,171.465 R118.2@159.296,171.465
USB_1_OC#: M1.B75 RA1.1 | length 6
  Top Layer w0.15: M1.B75@109.442,82.7 109.445,82.703 109.445,82.967 v1(110.05,83.571)
  Bottom Layer w0.15: RA1.1@108.9,88 108.9,86.85 110.05,85.7 v1(110.05,83.571)
USB_1_OC#_JMP: J3.17 J3B.9 JP1.1 | length 53.9
  Top Layer w0.15: JP1.1@139.42,183.236 v1(139.42,184.246) ; J3.17@144.58,134.43 J3B.9@144.58,139.51
  INT2_SIG w0.15: v1(139.42,184.246) 139.42,179.963 138.26,178.803 138.26,161.872 140.3,159.832 140.3,157.222 144.58,152.942 J3B.9@144.58,139.51
USB_1_SBU_N: J32.B8 M1.A67 U84.2 U84.9 | length 140.3
  Top Layer w0.15: M1.A67@114.523,84.9 114.523,84.923 114.355,85.091 114.355,114.706 117.7,118.051 117.7,142.125 132.175,156.6 132.175,179.084 132.962,179.871 132.962,181.47 133.187,181.695 v1(133.187,181.782) ; J32.B8@134,194.25 134,193.662 134.268,193.395 v4(134.268,193.3) ; v1(138.9,187.037) 139.022,187.037 139.199,186.86 139.841,186.86 140.2,187.219 140.2,187.995 140.1,188.095 U84.9@140.1,188.283 140.1,188.47 140.2,188.57 140.2,188.829 140.1,188.929 140.1,189.304 140.2,189.404 140.2,190.47 139.975,190.695 v1(139.975,190.783)
  Bottom Layer w0.15: 132.977,182.095 133.187,181.885 v1(133.187,181.782) 133.187,181.87 132.963,182.095 132.963,184.322 134.633,185.993 135.997,185.993 137.075,184.915 139.87,184.915 139.885,184.9 140.103,184.9 ; v4(134.268,193.3) 134.268,193.322 133.814,193.775 133.513,193.775 133.425,193.863 133.425,194.997 134.344,195.915 137.356,195.915 138.315,194.957 138.721,194.55 138.721,194.409 138.518,194.206 138.518,194.064 138.73,193.852 138.872,193.852 139.075,194.055 139.216,194.055 139.827,193.444 140.2,193.071 140.2,191.096 139.975,190.871 v1(139.975,190.783) 139.975,190.886 140.185,191.096 ; v1(138.9,187.037) 138.988,187.037 139.213,186.812 140.143,186.812 140.67,186.285 140.67,185.495 140.09,184.915 140.09,184.9
USB_1_SBU_P: J32.A8 M1.A68 U84.1 U84.10 | length 140.3
  Top Layer w0.15: M1.A68@113.888,84.9 113.888,84.923 114.055,85.091 114.055,114.83 117.4,118.175 117.4,142.249 131.875,156.724 131.875,179.208 132.662,179.995 132.662,181.47 132.437,181.695 v1(132.437,181.782) ; J32.A8@132.25,192.55 v4(132.25,193.35) ; v1(138.9,186.287) 138.94,186.287 139.213,186.56 139.965,186.56 140.5,187.095 140.5,187.995 140.6,188.095 U84.10@140.6,188.283 140.6,188.47 140.5,188.57 140.5,188.829 140.6,188.929 140.6,189.304 140.5,189.404 140.5,190.47 140.725,190.695 v1(140.725,190.783)
  Bottom Layer w0.15: v4(132.25,193.35) 132.675,193.775 133.037,193.775 133.125,193.863 133.125,195.121 134.22,196.215 137.48,196.215 140.5,193.195 140.5,191.096 140.725,190.871 v1(140.725,190.783) 140.725,190.886 140.515,191.096 ; 132.647,182.095 132.437,181.885 v1(132.437,181.782) 132.437,181.87 132.663,182.095 132.663,184.447 134.509,186.293 136.121,186.293 137.2,185.215 139.87,185.215 139.885,185.23 139.981,185.23 140.37,185.619 140.37,186.161 140.019,186.512 139.213,186.512 138.988,186.287 v1(138.9,186.287)
USB_1_SSRX1_N: L22.2 M1.A61 | length 110.9
  Top Layer w0.15: M1.A61@118.333,84.9 118.333,84.923 118.165,85.091 118.165,103.761 118.165,104.621 117.869,104.917 117.749,105.037 117.749,105.397 117.869,105.517 118.417,105.517 118.713,105.813 118.713,106.421 118.417,106.717 118.285,106.717 118.165,106.837 118.165,107 118.165,113.199 120,115.034 120,141.645 133.85,155.495 133.85,177.674 135.65,179.474 135.65,181.937 137.55,183.837 137.55,186.287 137.575,186.312 137.575,186.4 L22.2@137.65,186.475
USB_1_SSRX1_P: L22.1 M1.A62 | length 110.9
  Top Layer w0.15: M1.A62@117.698,84.9 117.698,84.923 117.865,85.091 117.865,103.761 117.865,104.497 117.745,104.617 117.449,104.913 117.449,105.521 117.745,105.817 118.293,105.817 118.413,105.937 118.413,106.297 118.293,106.417 118.161,106.417 117.865,106.713 117.865,107 117.865,113.323 119.7,115.158 119.7,141.769 133.55,155.619 133.55,177.798 135.35,179.598 135.35,182.061 137.25,183.961 137.25,186.287 137.225,186.312 137.225,186.4 L22.1@137.15,186.475
USB_1_SSRX2_N: L28.2 M1.A73 | length 115.8
  Top Layer w0.15: M1.A73@110.713,84.9 110.713,84.923 110.545,85.091 110.545,89.232 110.545,90.701 110.665,90.821 111.164,90.821 111.459,91.117 111.459,91.725 111.164,92.021 110.264,92.021 110.144,92.141 110.144,92.501 110.264,92.621 111.164,92.621 111.459,92.917 111.459,93.525 111.164,93.821 110.264,93.821 110.144,93.941 110.144,94.301 110.264,94.421 111.164,94.421 111.459,94.717 111.459,95.325 111.164,95.621 110.665,95.621 110.545,95.741 110.545,95.904 110.545,116.645 115.546,121.646 115.546,142.591 130.45,157.495 130.45,184.704 131.05,185.304 131.05,186.287 131.075,186.312 131.075,186.4 L28.2@131.15,186.475
USB_1_SSRX2_P: L28.1 M1.A74 | length 115.8
  Top Layer w0.15: M1.A74@110.078,84.9 110.078,84.923 110.245,85.091 110.245,89.232 110.245,90.825 110.541,91.121 111.039,91.121 111.159,91.241 111.159,91.601 111.039,91.721 110.14,91.721 109.844,92.017 109.844,92.625 110.14,92.921 111.039,92.921 111.159,93.041 111.159,93.401 111.039,93.521 110.14,93.521 109.844,93.817 109.844,94.425 110.14,94.721 111.039,94.721 111.159,94.841 111.159,95.201 111.039,95.321 110.541,95.321 110.245,95.617 110.245,95.904 110.245,116.769 115.246,121.77 115.246,142.715 130.15,157.619 130.15,184.828 130.75,185.428 130.75,186.287 130.725,186.312 130.725,186.4 L28.1@130.65,186.475
USB_1_SSTX1_N: L23.1 M1.A65 | length 115.5
  Top Layer w0.15: M1.A65@115.793,84.9 115.803,84.9 116.025,85.122 116.025,90.642 116.025,91.672 116.321,91.968 116.441,92.088 116.441,92.448 116.321,92.568 115.697,92.568 115.401,92.863 115.401,93.472 115.697,93.768 116.775,93.768 116.895,93.888 116.895,94.248 116.775,94.368 115.54,94.368 115.244,94.663 115.244,95.272 115.54,95.568 116.775,95.568 116.895,95.688 116.895,96.048 116.775,96.168 116.321,96.168 116.025,96.463 116.025,96.751 116.025,114.025 118.509,116.509 118.509,142.078 132.708,156.277 132.708,178.37 134.45,180.112 134.45,182.445 135.725,183.72 135.725,186.287 135.7,186.312 135.7,186.4 L23.1@135.625,186.475
USB_1_SSTX1_P: L23.2 M1.A64 | length 115.5
  Top Layer w0.15: M1.A64@116.428,84.9 116.428,84.956 116.325,85.058 116.325,90.642 116.325,91.548 116.445,91.668 116.741,91.963 116.741,92.572 116.445,92.868 115.821,92.868 115.701,92.988 115.701,93.348 115.821,93.468 116.9,93.468 117.195,93.763 117.195,94.372 116.9,94.668 115.664,94.668 115.544,94.788 115.544,95.148 115.664,95.268 116.9,95.268 117.195,95.563 117.195,96.172 116.9,96.468 116.445,96.468 116.325,96.588 116.325,96.751 116.325,113.901 118.809,116.384 118.809,141.954 133.008,156.153 133.008,178.246 134.75,179.988 134.75,182.321 136.025,183.596 136.025,186.287 136.05,186.312 136.05,186.4 L23.2@136.125,186.475
USB_1_SSTX2_N: L29.1 M1.A77 | length 110.3
  Top Layer w0.15: M1.A77@108.173,84.9 108.173,84.923 108.34,85.091 108.34,117.564 114.129,123.353 114.129,142.955 129.25,158.076 129.25,186.287 129.225,186.312 129.225,186.4 L29.1@129.15,186.475
USB_1_SSTX2_P: L29.2 M1.A76 | length 110.3
  Top Layer w0.15: M1.A76@108.808,84.9 108.808,84.923 108.64,85.091 108.64,117.44 114.429,123.229 114.429,142.831 129.55,157.952 129.55,186.287 129.575,186.312 129.575,186.4 L29.2@129.65,186.475
USB_1_VBUS: M1.B76 RA19.4 | length 7.6
  Top Layer w0.15: v1(107.55,84.186) 107.563,84.2 108.275,84.2 108.807,83.668 M1.B76@108.807,82.7
  Bottom Layer w0.15: RA19.4@105.05,88.25 105.05,86.686 v1(107.55,84.186)
USB_1_VBUS_JMP: J3.15 J3B.8 R114.2 R452.2 | length 49.9
  Top Layer w0.15: R452.2@145.19,181.81 R114.2@146.14,181.81 146.14,180.585 148.03,178.695 v1(148.03,169.632) ; J3.15@147.12,134.43 J3B.8@147.12,139.51
  INT2_SIG w0.15: J3B.8@147.12,139.51 147.12,155.52 148.5,156.9 148.5,159.1 148.038,159.562 148.038,169.625 v1(148.03,169.632)
USB_2_D_N: M1.A85 U27.46 | length 83
  Top Layer w0.15: U27.46@102.995,161.893 103.022,161.866 103.378,161.866 103.401,161.843 104.253,161.843 106.875,159.22 106.875,153.366 109.321,150.92 109.321,124.041 102.925,117.644 102.925,85.091 103.093,84.923 M1.A85@103.093,84.9
USB_2_D_P: M1.A86 U27.45 | length 83
  Top Layer w0.15: M1.A86@102.458,84.9 102.458,84.923 102.625,85.091 102.625,117.769 109.021,124.165 109.021,150.796 106.575,153.242 106.575,159.096 105.236,160.435 105.183,160.488 105.042,160.488 104.925,160.37 104.783,160.37 104.571,160.583 104.571,160.724 104.688,160.841 104.688,160.983 104.411,161.26 104.128,161.543 103.401,161.543 103.378,161.52 103.022,161.52 U27.45@102.995,161.493
USB_2_EN: M1.B80 RA19.2 | length 11.3
  Top Layer w0.15: M1.B80@106.267,82.7 106.267,82.144 v1(107.485,80.926)
  Bottom Layer w0.15: RA19.2@106.05,88.25 106.057,88.242 106.057,87.739 108.1,85.697 108.1,84.998 108.807,84.291 108.807,83.02 107.485,81.698 v1(107.485,80.926)
USB_2_EN_JMP: J3.11 J3B.6 R213.2 | length 76.9
  Top Layer w0.15: R213.2@87.32,146.886 87.32,146.369 87.579,146.11 94.343,146.11 v1(95.203,146.97) ; v1(136.705,145.938) 139.943,142.7 149.01,142.7 J3B.6@152.2,139.51 J3.11@152.2,134.43
  INT2_SIG w0.15: v1(95.203,146.97) 97.032,148.799 103.471,148.799 104.902,150.23 126.085,150.23 130.556,145.759 136.405,145.759 136.583,145.938 v1(136.705,145.938)
USB_2_SSRX1_N: C120.1 M1.A82 | length 84
  Top Layer w0.15: M1.A82@104.998,84.9 104.998,84.923 104.83,85.091 104.83,92.033 104.83,93.001 104.534,93.296 104.414,93.416 104.414,93.776 104.534,93.896 105.132,93.896 105.427,94.192 105.427,94.801 105.132,95.096 104.95,95.096 104.83,95.216 104.83,95.379 104.83,117.675 110.9,123.745 110.9,151.761 107.897,154.765 107.897,161.874 107.114,162.657 106.65,162.657 106.467,162.839 C120.1@106.467,162.939
USB_2_SSRX1_P: C117.1 M1.A83 | length 84
  Top Layer w0.15: M1.A83@104.363,84.9 104.363,84.923 104.53,85.091 104.53,92.033 104.53,92.876 104.41,92.996 104.114,93.292 104.114,93.901 104.41,94.196 105.007,94.196 105.127,94.316 105.127,94.676 105.007,94.796 104.826,94.796 104.53,95.092 104.53,95.379 104.53,117.799 110.6,123.869 110.6,151.637 107.597,154.64 107.597,160.649 107.597,160.724 107.497,160.824 107.304,160.824 107.204,160.924 107.204,161.224 107.304,161.324 107.497,161.324 107.597,161.424 107.597,161.73 107.597,161.75 106.989,162.357 106.65,162.357 C117.1@106.467,162.175
USB_2_SSTX1_N: M1.A79 R462.1 | length 4.7
  Top Layer w0.15: M1.A79@106.903,84.9 106.903,84.923 106.735,85.091 106.735,87.001 106.76,87.026 106.76,88.987 106.848,89.075 106.91,89.075 R462.1@107.135,89.3
USB_2_SSTX1_P: M1.A80 R461.1 | length 4.7
  Top Layer w0.15: R461.1@106.085,89.3 106.31,89.075 106.373,89.075 106.46,88.987 106.46,87.15 106.435,87.125 106.435,85.091 106.268,84.923 M1.A80@106.268,84.9
USB_3_CC1: R436.2 U95.1 | length 10
  Top Layer w0.15: U95.1@112.566,174.261 113.945,174.261 114.17,174.485 115.705,174.485 116.438,175.218 116.438,175.429 117.245,176.237 117.245,177.73 117.014,177.962 115.708,177.962 114.889,177.144 R436.2@114.889,177.094
USB_3_CC2: R437.2 U95.2 | length 5.8
  Top Layer w0.15: U95.2@112.566,174.661 113.921,174.661 114.046,174.785 115.581,174.785 116.001,175.205 116.001,175.416 116.495,175.911 R437.2@116.495,177.112
USB_3_N: J72.A7 J72.B7 L99.4 U100.5 U100.6 | length 11.4
  Top Layer w0.15: L99.4@119.5,186.75 119.5,186.925 119.625,187.05 119.687,187.05 119.775,187.138 119.775,187.996 119.675,188.096 U100.6@119.675,188.283 119.675,188.471 119.775,188.571 119.775,188.83 119.675,188.93 119.675,189.305 119.775,189.405 119.775,190.13 119.807,190.163 119.807,191.132 119.582,191.357 119.582,191.567 119.75,191.735 J72.A7@119.75,192.55 ; J72.B7@120.5,194.25 120.425,194.175 120.425,193.895 120.417,193.887 120.417,193.563 120.618,193.363 v4(120.618,193.3)
  Bottom Layer w0.15: v1(119.582,191.445) 119.582,192.079 119.675,192.171 119.675,192.357 119.918,192.6 120.059,192.6 120.627,192.033 120.768,192.033 120.909,192.174 120.909,192.316 120.342,192.883 120.342,193.025 v4(120.618,193.3)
